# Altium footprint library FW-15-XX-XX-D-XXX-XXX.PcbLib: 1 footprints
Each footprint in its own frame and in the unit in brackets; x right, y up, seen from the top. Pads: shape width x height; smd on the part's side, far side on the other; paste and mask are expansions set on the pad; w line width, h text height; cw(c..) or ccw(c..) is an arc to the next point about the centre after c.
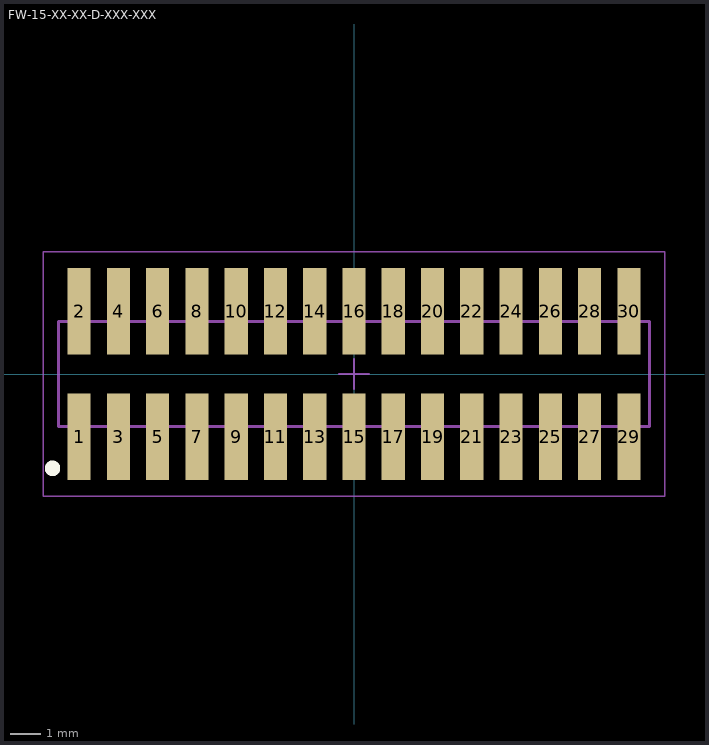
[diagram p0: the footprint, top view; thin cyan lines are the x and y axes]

## FW-15-XX-XX-D-XXX-XXX [mm] "1.27mm pitch, 30 pin, board stacker; SMT"
height 2.92
pads (30):
  rect 0.75x2.8 smd mask+0: 1(-8.89,-2.032) 2(-8.89,2.032) 3(-7.62,-2.032) 4(-7.62,2.032) 5(-6.35,-2.032) 6(-6.35,2.032) 7(-5.08,-2.032) 8(-5.08,2.032) 9(-3.81,-2.032) 10(-3.81,2.032) 11(-2.54,-2.032) 12(-2.54,2.032) 13(-1.27,-2.032) 14(-1.27,2.032) 15(0,-2.032) 16(0,2.032) 17(1.27,-2.032) 18(1.27,2.032) 19(2.54,-2.032) 20(2.54,2.032) 21(3.81,-2.032) 22(3.81,2.032) 23(5.08,-2.032) 24(5.08,2.032) 25(6.35,-2.032) 26(6.35,2.032) 27(7.62,-2.032) 28(7.62,2.032) 29(8.89,-2.032) 30(8.89,2.032)
Top Overlay:
  circle w0.25: c-9.75,-3.05 r0.125
Mechanical 12:
  lines w0.001: -9.55,-1.7 9.55,-1.7 9.55,1.7 -9.55,1.7 -9.55,-1.7
Mechanical 13:
  lines w0.1: -9.55,-1.7 9.55,-1.7 9.55,1.7 -9.55,1.7 -9.55,-1.7
  text ".Designator" at 0.254,0.254 h1.52
Mechanical 15:
  lines w0.05: -0.5,0 0.5,0 ; 0,-0.5 0,0.5 ; -10.05,-3.95 10.05,-3.95 10.05,3.95 -10.05,3.95 -10.05,-3.95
